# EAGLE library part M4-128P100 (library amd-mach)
AMD MACH SERIES
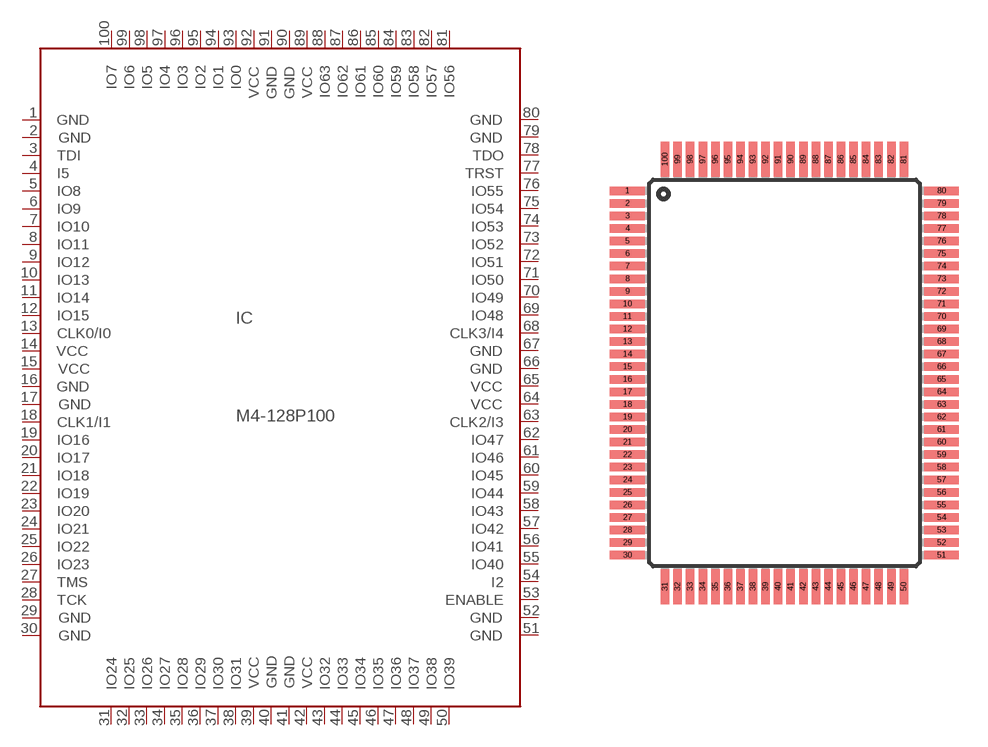
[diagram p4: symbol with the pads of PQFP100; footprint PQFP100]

Designator prefix IC

## M4-128P100 (OC_FARNELL: unknown; OC_NEWARK: unknown)  [PQFP100]
1  GND  pwr
2  GND  pwr
3  TDI  in
4  I5  in
5  IO8
6  IO9
7  IO10
8  IO11
9  IO12
10  IO13
11  IO14
12  IO15
13  CLK0/I0  in
14  VCC  pwr
15  VCC  pwr
16  GND  pwr
17  GND  pwr
18  CLK1/I1  in
19  IO16
20  IO17
21  IO18
22  IO19
23  IO20
24  IO21
25  IO22
26  IO23
27  TMS  in
28  TCK  in
29  GND  pwr
30  GND  pwr
31  IO24
32  IO25
33  IO26
34  IO27
35  IO28
36  IO29
37  IO30
38  IO31
39  VCC  pwr
40  GND  pwr
41  GND  pwr
42  VCC  pwr
43  IO32
44  IO33
45  IO34
46  IO35
47  IO36
48  IO37
49  IO38
50  IO39
51  GND  pwr
52  GND  pwr
53  ENABLE  in
54  I2  in
55  IO40
56  IO41
57  IO42
58  IO43
59  IO44
60  IO45
61  IO46
62  IO47
63  CLK2/I3  in
64  VCC  pwr
65  VCC  pwr
66  GND  pwr
67  GND  pwr
68  CLK3/I4  in
69  IO48
70  IO49
71  IO50
72  IO51
73  IO52
74  IO53
75  IO54
76  IO55
77  TRST  in
78  TDO  out
79  GND  pwr
80  GND  pwr
81  IO56
82  IO57
83  IO58
84  IO59
85  IO60
86  IO61
87  IO62
88  IO63
89  VCC  pwr
90  GND  pwr
91  GND  pwr
92  VCC  pwr
93  IO0
94  IO1
95  IO2
96  IO3
97  IO4
98  IO5
99  IO6
100  IO7

## Footprint PQFP100 (pad centres in mm)
PLASTIC QUAD FLAT PACK
smd 1.8 x 0.44: 1 -8.125,9.425; 2 -8.125,8.775; 3 -8.125,8.125; 4 -8.125,7.475; 5 -8.125,6.825; 6 -8.125,6.175; 7 -8.125,5.525; 8 -8.125,4.875; 9 -8.125,4.225; 10 -8.125,3.575; 11 -8.125,2.925; 12 -8.125,2.275; 13 -8.125,1.625; 14 -8.125,0.975; 15 -8.125,0.325; 16 -8.125,-0.325; 17 -8.125,-0.975; 18 -8.125,-1.625; 19 -8.125,-2.275; 20 -8.125,-2.925; 21 -8.125,-3.575; 22 -8.125,-4.225; 23 -8.125,-4.875; 24 -8.125,-5.525; 25 -8.125,-6.175; 26 -8.125,-6.825; 27 -8.125,-7.475; 28 -8.125,-8.125; 29 -8.125,-8.775; 30 -8.125,-9.425; 51 8.125,-9.425; 52 8.125,-8.775; 53 8.125,-8.125; 54 8.125,-7.475; 55 8.125,-6.825; 56 8.125,-6.175; 57 8.125,-5.525; 58 8.125,-4.875; 59 8.125,-4.225; 60 8.125,-3.575; 61 8.125,-2.925; 62 8.125,-2.275; 63 8.125,-1.625; 64 8.125,-0.975; 65 8.125,-0.325; 66 8.125,0.325; 67 8.125,0.975; 68 8.125,1.625; 69 8.125,2.275; 70 8.125,2.925; 71 8.125,3.575; 72 8.125,4.225; 73 8.125,4.875; 74 8.125,5.525; 75 8.125,6.175; 76 8.125,6.825; 77 8.125,7.475; 78 8.125,8.125; 79 8.125,8.775; 80 8.125,9.425
smd 0.44 x 1.8: 31 -6.175,-11.05; 32 -5.525,-11.05; 33 -4.875,-11.05; 34 -4.225,-11.05; 35 -3.575,-11.05; 36 -2.925,-11.05; 37 -2.275,-11.05; 38 -1.625,-11.05; 39 -0.975,-11.05; 40 -0.325,-11.05; 41 0.325,-11.05; 42 0.975,-11.05; 43 1.625,-11.05; 44 2.275,-11.05; 45 2.925,-11.05; 46 3.575,-11.05; 47 4.225,-11.05; 48 4.875,-11.05; 49 5.525,-11.05; 50 6.175,-11.05; 81 6.175,11.05; 82 5.525,11.05; 83 4.875,11.05; 84 4.225,11.05; 85 3.575,11.05; 86 2.925,11.05; 87 2.275,11.05; 88 1.625,11.05; 89 0.975,11.05; 90 0.325,11.05; 91 -0.325,11.05; 92 -0.975,11.05; 93 -1.625,11.05; 94 -2.275,11.05; 95 -2.925,11.05; 96 -3.575,11.05; 97 -4.225,11.05; 98 -4.875,11.05; 99 -5.525,11.05; 100 -6.175,11.05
